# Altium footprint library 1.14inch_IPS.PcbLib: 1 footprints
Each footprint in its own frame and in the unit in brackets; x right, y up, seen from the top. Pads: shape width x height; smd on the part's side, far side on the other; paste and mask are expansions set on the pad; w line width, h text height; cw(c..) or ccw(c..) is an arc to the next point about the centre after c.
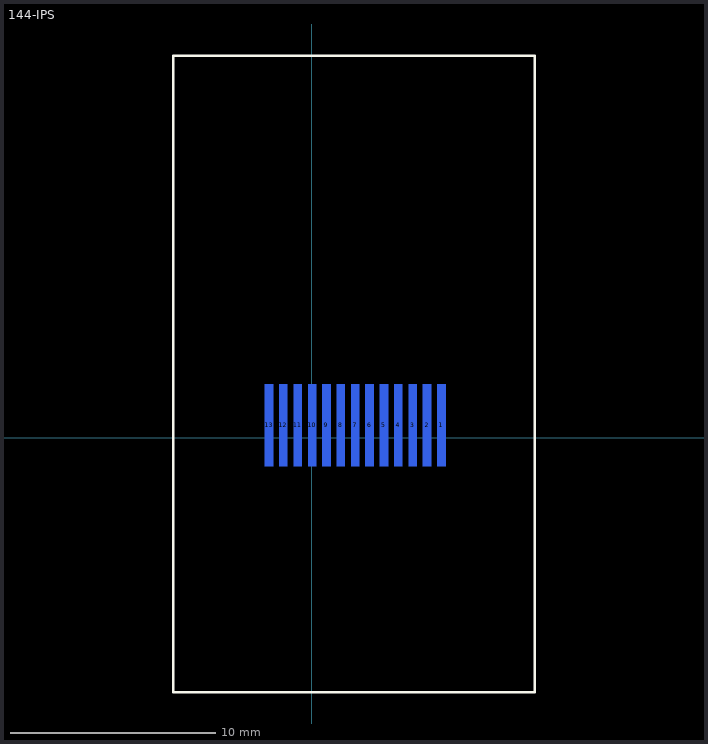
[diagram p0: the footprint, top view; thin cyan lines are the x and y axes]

## 144-IPS [mm] "1.44 TFT IPS"
pads (13):
  rect 0.4x4 smd far side: 1(6.31,0.6) 2(5.61,0.6) 3(4.91,0.6) 4(4.21,0.6) 5(3.51,0.6) 6(2.81,0.6) 7(2.11,0.6) 8(1.41,0.6) 9(0.71,0.6) 10(0.01,0.6) 11(-0.69,0.6) 12(-1.39,0.6) 13(-2.09,0.6)
Top Overlay:
  lines w0.127: -6.75,18.598 10.85,18.598 ; -6.75,18.6 -6.75,-12.4 10.85,-12.4 10.85,18.6
Bottom Overlay:
  lines w0.127: -4.09,-1.4 -4.09,0.6 -2.667,0.6 ; 6.858,0.6 8.31,0.6 8.31,-1.4
  text "1" at 7.754,0.872 h0.76
  text "13" at -2.901,0.915 h0.76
